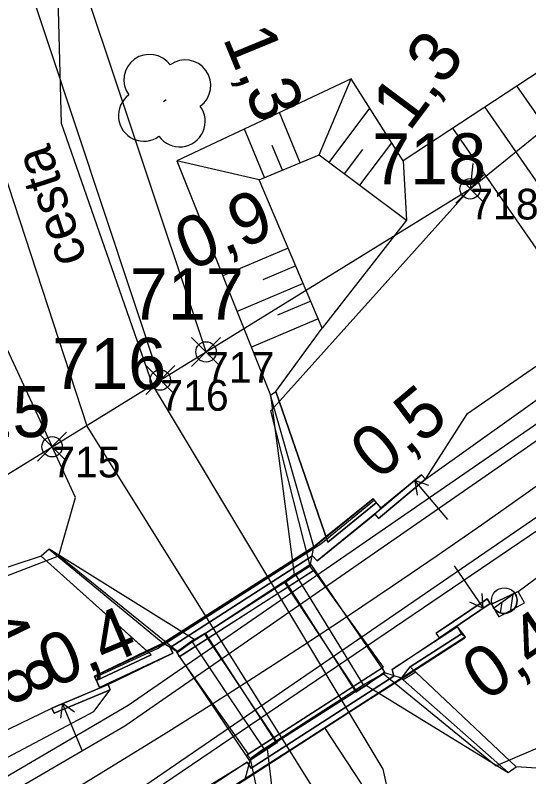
# Model space of a CAD drawing. Extents: x -800194 to -799078, y -1007177 to -1006597.
# Drawn here: x -799502.31 to -799482.23, y -1006953.32 to -1006923.53 of the extents above; entities that cross this region are included whole.
import ezdxf

# ---------------------------------------------------------------- set-up
doc = ezdxf.new("R2010")
doc.units = 0
for name, color, linetype in [('02_Osa_koleje', 7, 'Continuous'), ('Obvod stavby', 7, 'Continuous'), ('Vrstva 11', 7, 'Continuous'), ('Vrstva 12', 7, 'Continuous'), ('Vrstva 13', 7, 'Continuous'), ('Vrstva 17', 7, 'Continuous'), ('Vrstva 18', 7, 'Continuous'), ('Vrstva 4', 7, 'Continuous'), ('Vrstva 48', 7, 'Continuous'), ('Vrstva 49', 7, 'Continuous'), ('Vrstva 50', 7, 'Continuous'), ('Vrstva 51', 7, 'Continuous'), ('Vrstva 53', 7, 'Continuous'), ('Vrstva 55', 7, 'Continuous'), ('Vrstva 56', 7, 'Continuous'), ('Vrstva 60', 7, 'Continuous')]:
    doc.layers.add(name, color=color, linetype=linetype)

msp = doc.modelspace()

# ---------------------------------------------------------------- linework, layer by layer
at = {"layer": '02_Osa_koleje'}
msp.add_arc((-799651.022, -1006703.891), 292, 255.62486, 308.20516, dxfattribs=at)
at = {"layer": 'Obvod stavby'}
for p, q in [((-799485.086, -1006930.886), (-799483.954, -1006929.754)), ((-799485.086, -1006929.754), (-799483.954, -1006930.886)), ((-799495.416, -1006937.266), (-799494.284, -1006936.134)), ((-799495.416, -1006936.134), (-799494.284, -1006937.266)), ((-799497.206, -1006938.366), (-799496.074, -1006937.234)), ((-799497.206, -1006937.234), (-799496.074, -1006938.366)), ((-799501.436, -1006940.976), (-799500.304, -1006939.844)), ((-799501.436, -1006939.844), (-799500.304, -1006940.976))]:
    msp.add_line(p, q, dxfattribs=at)
msp.add_lwpolyline([(-799559.64, -1006968.48), (-799519.68, -1006952.01), (-799500.87, -1006940.41), (-799496.64, -1006937.8), (-799494.85, -1006936.7), (-799484.52, -1006930.32), (-799457.99, -1006908.8), (-799435, -1006885.17), (-799430.26, -1006880.27), (-799425.53, -1006875.38), (-799422.55, -1006864.36), (-799416.748, -1006858.798), (-799395.763, -1006879.374), (-799413.75, -1006898.23), (-799418.41, -1006902.53), (-799423.07, -1006906.83), (-799433.4, -1006916.39), (-799469.5, -1006946.86), (-799487.22, -1006958.47), (-799495.25, -1006963.74), (-799521.98, -1006977.8), (-799546.71, -1006987.83)], dxfattribs=at)
for centre in [(-799484.52, -1006930.32), (-799494.85, -1006936.7), (-799496.64, -1006937.8), (-799500.87, -1006940.41)]:
    msp.add_circle(centre, 0.4, dxfattribs=at)
at = {"layer": 'Vrstva 11'}
for p, q in [((-799482.779, -1006946.134), (-799483.593, -1006946.726)), ((-799482.944, -1006946.87), (-799482.835, -1006946.174)), ((-799483.33, -1006946.908), (-799483.264, -1006946.487))]:
    msp.add_line(p, q, dxfattribs=at)
msp.add_circle((-799483.186, -1006946.43), 0.503, dxfattribs=at)
msp.add_arc((-799483.186, -1006946.43), 0.503, 216.0719, 36.0719, dxfattribs=at)
at = {"layer": 'Vrstva 12'}
for p, q in [((-799482.39, -1006946.51), (-799482.389, -1006946.51)), ((-799483.395, -1006947.061), (-799483.396, -1006947.063))]:
    msp.add_line(p, q, dxfattribs=at)
for points in [[(-799483.686, -1006946.569), (-799483.395, -1006947.061), (-799482.39, -1006946.51), (-799482.647, -1006946.068), (-799483.686, -1006946.569)], [(-799483.686, -1006946.569), (-799483.396, -1006947.063), (-799482.389, -1006946.51), (-799482.647, -1006946.068)]]:
    msp.add_lwpolyline(points, dxfattribs=at)
at = {"layer": 'Vrstva 13'}
for p, q in [((-799486.269, -1006941.68), (-799488.105, -1006943.216)), ((-799485.395, -1006943.261), (-799486.684, -1006941.731)), ((-799485.14, -1006945.073), (-799484.016, -1006946.727)), ((-799483.858, -1006946.36), (-799485.847, -1006947.698)), ((-799498.68, -1006949.706), (-799498.679, -1006949.705)), ((-799498.598, -1006949.914), (-799498.598, -1006949.914)), ((-799499.688, -1006952.297), (-799500.461, -1006950.453)), ((-799500.882, -1006950.629), (-799500.879, -1006950.629)), ((-799500.794, -1006950.828), (-799500.793, -1006950.828))]:
    msp.add_line(p, q, dxfattribs=at)
for points in [[(-799486.419, -1006941.508), (-799488.011, -1006942.815), (-799488.249, -1006943.052)], [(-799486.419, -1006941.508), (-799487.989, -1006942.83), (-799488.249, -1006943.052), (-799488.105, -1006943.216), (-799486.271, -1006941.68), (-799486.419, -1006941.508)], [(-799486.271, -1006941.68), (-799486.269, -1006941.68), (-799486.419, -1006941.508), (-799486.419, -1006941.508)], [(-799486.132, -1006941.92), (-799486.684, -1006941.731), (-799486.591, -1006942.307)], [(-799484.545, -1006946.482), (-799484.016, -1006946.727), (-799484.049, -1006946.145)], [(-799485.713, -1006947.881), (-799485.847, -1006947.698), (-799483.855, -1006946.358), (-799483.733, -1006946.535), (-799485.713, -1006947.881)], [(-799483.734, -1006946.536), (-799483.858, -1006946.36), (-799483.855, -1006946.358)], [(-799485.713, -1006947.881), (-799483.734, -1006946.536), (-799483.733, -1006946.535)], [(-799498.598, -1006949.914), (-799500.793, -1006950.828), (-799500.882, -1006950.629), (-799498.68, -1006949.706), (-799498.598, -1006949.914)], [(-799498.598, -1006949.914), (-799498.679, -1006949.705), (-799500.879, -1006950.629), (-799500.794, -1006950.828), (-799498.598, -1006949.914)], [(-799499.991, -1006950.798), (-799500.461, -1006950.453), (-799500.545, -1006951.03)]]:
    msp.add_lwpolyline(points, dxfattribs=at)
at = {"layer": 'Vrstva 17'}
for points in [[(-799499.208, -1006949.438), (-799496.75, -1006948.302), (-799490.358, -1006944.213), (-799488.261, -1006942.491)], [(-799495.74, -1006954.93), (-799493.422, -1006953.452), (-799487.055, -1006949.386), (-799484.733, -1006947.883)]]:
    msp.add_lwpolyline(points, dxfattribs=at)
at = {"layer": 'Vrstva 18'}
for p, q in [((-799490.09, -1006944.145), (-799492.124, -1006938.252)), ((-799488.314, -1006942.445), (-799490.161, -1006943.939)), ((-799490.09, -1006944.145), (-799488.194, -1006942.597)), ((-799490.161, -1006943.939), (-799490.09, -1006944.145)), ((-799490.633, -1006944.324), (-799496.528, -1006948.097)), ((-799490.776, -1006945.086), (-799490.633, -1006944.324)), ((-799490.622, -1006944.331), (-799490.633, -1006944.324)), ((-799500.989, -1006944.417), (-799496.528, -1006948.097)), ((-799496.989, -1006948.551), (-799501.292, -1006944.69)), ((-799495.895, -1006948.622), (-799490.655, -1006945.247)), ((-799490.776, -1006945.086), (-799490.751, -1006945.022)), ((-799490.751, -1006945.022), (-799487.865, -1006949.228)), ((-799490.653, -1006945.248), (-799487.917, -1006949.036)), ((-799488.956, -1006949.979), (-799491.774, -1006945.715)), ((-799491.751, -1006945.671), (-799488.989, -1006950.004)), ((-799495.31, -1006947.953), (-799494.911, -1006947.721)), ((-799494.911, -1006947.721), (-799494.886, -1006947.696)), ((-799492.072, -1006951.961), (-799494.911, -1006947.721)), ((-799494.886, -1006947.697), (-799492.091, -1006951.998)), ((-799484.86, -1006947.727), (-799484.859, -1006947.724)), ((-799496.528, -1006948.097), (-799496.531, -1006948.126)), ((-799497.167, -1006948.391), (-799496.989, -1006948.551)), ((-799495.983, -1006948.431), (-799495.999, -1006948.451)), ((-799495.999, -1006948.451), (-799493.155, -1006952.694)), ((-799499.136, -1006949.559), (-799496.989, -1006948.551)), ((-799495.895, -1006948.62), (-799493.202, -1006952.432)), ((-799487.948, -1006949.054), (-799493.246, -1006952.463)), ((-799493.202, -1006952.432), (-799487.917, -1006949.036)), ((-799487.208, -1006949.465), (-799486.865, -1006949.018)), ((-799482.72, -1006952.931), (-799486.865, -1006949.018)), ((-799486.646, -1006949.224), (-799486.865, -1006949.018)), ((-799487.862, -1006949.253), (-799487.865, -1006949.228)), ((-799487.208, -1006949.465), (-799487.862, -1006949.253)), ((-799487.142, -1006949.523), (-799487.208, -1006949.465)), ((-799488.571, -1006949.746), (-799483.04, -1006953.154)), ((-799458.168, -1007000.066), (-799490.201, -1006951.402)), ((-799493.105, -1006952.61), (-799493.33, -1006953.427))]:
    msp.add_line(p, q, dxfattribs=at)
for points in [[(-799492.323, -1006938.391), (-799492.124, -1006938.252), (-799490.161, -1006943.939), (-799490.633, -1006944.324), (-799492.323, -1006938.391), (-799491.402, -1006945.404), (-799490.751, -1006945.022)], [(-799487.989, -1006942.83), (-799490.497, -1006944.878), (-799490.687, -1006944.683), (-799496.251, -1006948.258), (-799496.151, -1006948.479), (-799499.016, -1006949.821), (-799499.21, -1006949.384), (-799496.531, -1006948.126), (-799490.622, -1006944.331), (-799488.313, -1006942.446)], [(-799488.313, -1006942.446), (-799488.314, -1006942.445), (-799488.194, -1006942.597), (-799488.194, -1006942.597), (-799488.011, -1006942.815), (-799488.011, -1006942.815), (-799487.989, -1006942.83), (-799488.313, -1006942.446)], [(-799488.194, -1006942.597), (-799490.09, -1006944.145), (-799490.09, -1006944.145)], [(-799495.31, -1006947.953), (-799500.989, -1006944.417), (-799501.292, -1006944.69)], [(-799495.983, -1006948.431), (-799496.528, -1006948.097), (-799497.167, -1006948.391), (-799501.292, -1006944.69)], [(-799495.895, -1006948.62), (-799490.653, -1006945.248), (-799490.655, -1006945.247), (-799490.776, -1006945.086), (-799495.983, -1006948.431)], [(-799491.402, -1006945.404), (-799491.751, -1006945.671), (-799491.774, -1006945.715), (-799490.751, -1006945.022)], [(-799485.016, -1006947.459), (-799487.565, -1006949.124), (-799487.499, -1006949.378), (-799493.081, -1006952.976), (-799493.236, -1006952.753), (-799495.947, -1006954.533), (-799495.696, -1006954.958), (-799484.706, -1006947.846)], [(-799484.859, -1006947.724), (-799484.706, -1006947.846), (-799484.706, -1006947.846), (-799485.016, -1006947.459), (-799485.016, -1006947.459), (-799484.86, -1006947.727)], [(-799495.31, -1006947.953), (-799495.999, -1006948.451), (-799494.886, -1006947.697), (-799494.886, -1006947.696)], [(-799484.706, -1006947.846), (-799487.208, -1006949.465), (-799493.33, -1006953.427), (-799495.696, -1006954.958), (-799495.696, -1006954.958)], [(-799486.865, -1006949.018), (-799484.859, -1006947.724)], [(-799484.86, -1006947.727), (-799486.865, -1006949.018), (-799486.865, -1006949.018)], [(-799497.167, -1006948.391), (-799499.209, -1006949.385), (-799499.21, -1006949.384)], [(-799495.895, -1006948.62), (-799495.895, -1006948.622), (-799495.983, -1006948.431)], [(-799496.989, -1006948.551), (-799496.989, -1006948.551), (-799499.13, -1006949.555)], [(-799493.155, -1006952.694), (-799493.105, -1006952.61), (-799487.862, -1006949.253), (-799487.948, -1006949.054), (-799487.917, -1006949.036)], [(-799499.209, -1006949.385), (-799499.136, -1006949.559), (-799499.13, -1006949.555), (-799499.015, -1006949.821), (-799499.016, -1006949.821)], [(-799488.571, -1006949.746), (-799488.989, -1006950.004), (-799488.956, -1006949.979), (-799487.865, -1006949.228), (-799488.571, -1006949.746)], [(-799483.04, -1006953.154), (-799482.72, -1006952.931), (-799486.646, -1006949.224), (-799487.142, -1006949.523), (-799483.04, -1006953.154)], [(-799492.448, -1006952.232), (-799492.072, -1006951.961), (-799492.091, -1006951.998), (-799493.155, -1006952.694)], [(-799492.007, -1006959.466), (-799491.611, -1006959.287), (-799492.448, -1006952.232), (-799493.155, -1006952.694)], [(-799493.105, -1006952.61), (-799493.246, -1006952.463), (-799493.202, -1006952.432)]]:
    msp.add_lwpolyline(points, dxfattribs=at)
at = {"layer": 'Vrstva 4'}
for points in [[(-799510.394, -1006958.536), (-799498.027, -1006951.328), (-799477.988, -1006937.435), (-799460.33, -1006923.117), (-799451.862, -1006915.581), (-799443.604, -1006907.9), (-799435.444, -1006900.067), (-799428.64, -1006893.299), (-799422.817, -1006887.511), (-799415.998, -1006880.595), (-799408.158, -1006872.652), (-799401.02, -1006864.85)], [(-799509.248, -1006960.724), (-799497.456, -1006953.809), (-799476.495, -1006939.437), (-799458.707, -1006924.982), (-799450.277, -1006917.43), (-799441.932, -1006909.717), (-799433.783, -1006901.867), (-799426.9, -1006895.092), (-799421.037, -1006889.182), (-799414.218, -1006882.281), (-799406.443, -1006874.417), (-799398.609, -1006866.93)], [(-799511.236, -1006957.129), (-799499.236, -1006950.771), (-799498.598, -1006949.914), (-799498.679, -1006949.705), (-799496.151, -1006948.479), (-799496.251, -1006948.258), (-799490.687, -1006944.683), (-799490.497, -1006944.878), (-799488.249, -1006943.052), (-799488.105, -1006943.216), (-799486.269, -1006941.68), (-799478.997, -1006936.484), (-799474.568, -1006932.916), (-799474.237, -1006932.694), (-799461.519, -1006921.99), (-799452.935, -1006914.372), (-799444.695, -1006906.886), (-799436.579, -1006898.932), (-799429.629, -1006892.192), (-799429.07, -1006892.727), (-799423.479, -1006886.901), (-799416.56, -1006880.007), (-799417.085, -1006879.46), (-799415.349, -1006878.386)], [(-799510.726, -1006958.045), (-799497.901, -1006950.516), (-799478.36, -1006937.055), (-799461.534, -1006923.53), (-799452.128, -1006915.305), (-799443.894, -1006907.632), (-799435.739, -1006899.754), (-799428.922, -1006893.007), (-799423.223, -1006887.256), (-799416.277, -1006880.269), (-799414.896, -1006878.87)], [(-799509.087, -1006961.127), (-799497.277, -1006954.118), (-799476.183, -1006939.802), (-799458.586, -1006925.284), (-799449.914, -1006917.869), (-799441.499, -1006910.139), (-799433.371, -1006902.28), (-799426.451, -1006895.478), (-799420.657, -1006889.585), (-799413.85, -1006882.742), (-799412.388, -1006881.287)], [(-799507.817, -1006962.779), (-799497.104, -1006956.83), (-799497.4, -1006955.599), (-799497.585, -1006955.395), (-799495.628, -1006953.965), (-799495.505, -1006954.146), (-799493.236, -1006952.753), (-799493.081, -1006952.976), (-799487.499, -1006949.378), (-799487.565, -1006949.124), (-799485.713, -1006947.881), (-799485.847, -1006947.698), (-799483.858, -1006946.36), (-799483.734, -1006946.536), (-799483.686, -1006946.569), (-799482.647, -1006946.068), (-799475.489, -1006940.774), (-799457.684, -1006926.366)]]:
    msp.add_lwpolyline(points, dxfattribs=at)
at = {"layer": 'Vrstva 48'}
for p, q in [((-799477.319, -1006934.06), (-799482.69, -1006926.295)), ((-799491.172, -1006929.304), (-799491.98, -1006927.341)), ((-799490.032, -1006929.287), (-799488.444, -1006927.16)), ((-799478.552, -1006934.913), (-799483.943, -1006927.119)), ((-799479.786, -1006935.767), (-799485.197, -1006927.943)), ((-799492.559, -1006929.875), (-799493.339, -1006927.982)), ((-799488.83, -1006930.184), (-799487.586, -1006928.519)), ((-799491.865, -1006929.589), (-799492.262, -1006928.625)), ((-799489.431, -1006929.736), (-799488.723, -1006928.788)), ((-799491.636, -1006932.643), (-799494.189, -1006933.727)), ((-799491.343, -1006933.333), (-799492.626, -1006933.878)), ((-799491.05, -1006934.024), (-799493.632, -1006935.12)), ((-799490.757, -1006934.714), (-799492.055, -1006935.265)), ((-799490.463, -1006935.405), (-799493.074, -1006936.513))]:
    msp.add_line(p, q, dxfattribs=at)
at = {"layer": 'Vrstva 49'}
for p, q in [((-799490.423, -1006928.995), (-799489.168, -1006926.015)), ((-799492.773, -1006929.963), (-799495.987, -1006929.231)), ((-799492.124, -1006938.252), (-799490.308, -1006935.771))]:
    msp.add_line(p, q, dxfattribs=at)
for points in [[(-799429.125, -1006891.656), (-799433.133, -1006889.484), (-799437.572, -1006888.963), (-799439.693, -1006890.332), (-799461.15, -1006912.135), (-799487.142, -1006929.222), (-799487.006, -1006931.546), (-799490.308, -1006935.771)], [(-799490.09, -1006944.145), (-799488.194, -1006942.597), (-799488.011, -1006942.815), (-799488.011, -1006942.815), (-799486.419, -1006941.508), (-799486.269, -1006941.68), (-799484.618, -1006939.109), (-799474.926, -1006932.405), (-799474.596, -1006932.171), (-799461.519, -1006921.99), (-799452.935, -1006914.372), (-799445.566, -1006906.106), (-799432.588, -1006892.596), (-799429.125, -1006891.656)], [(-799486.865, -1006949.018), (-799484.86, -1006947.727), (-799485.016, -1006947.459), (-799485.713, -1006947.881), (-799483.734, -1006946.536), (-799483.686, -1006946.569), (-799483.396, -1006947.063), (-799482.389, -1006946.51), (-799482.647, -1006946.068), (-799475.489, -1006940.774), (-799464.892, -1006933.871), (-799456.989, -1006927.138), (-799455.117, -1006925.642), (-799440.165, -1006911.165), (-799428.918, -1006899.95), (-799428.299, -1006900.544), (-799427.466, -1006899.73), (-799428.131, -1006899.117), (-799426.509, -1006898.237), (-799425.17, -1006895.342)], [(-799423.903, -1006906.911), (-799427.313, -1006910.033), (-799439.866, -1006919.177), (-799453.667, -1006933.596), (-799478.523, -1006953.199), (-799482.72, -1006952.931), (-799486.865, -1006949.018)], [(-799487.142, -1006929.222), (-799489.168, -1006926.015), (-799495.987, -1006929.231), (-799492.323, -1006938.391), (-799492.124, -1006938.252)], [(-799490.308, -1006935.771), (-799492.773, -1006929.963), (-799490.423, -1006928.995), (-799487.006, -1006931.546)], [(-799492.124, -1006938.252), (-799490.09, -1006944.145)], [(-799496.989, -1006948.551), (-799501.292, -1006944.69), (-799510.22, -1006947.622)], [(-799512.053, -1006955.956), (-799509.8, -1006954.937), (-799509.204, -1006954.659), (-799500.879, -1006950.629), (-799498.679, -1006949.705), (-799499.015, -1006949.821), (-799499.13, -1006949.555), (-799496.989, -1006948.551)]]:
    msp.add_lwpolyline(points, dxfattribs=at)
at = {"layer": 'Vrstva 50'}
msp.add_line((-799496.517, -1006926.907), (-799496.403, -1006926.823), dxfattribs=at)
for centre, start, end in [((-799497.059, -1006926.062), 36.0719, 216.0719), ((-799495.662, -1006926.281), 306.0719, 126.0719), ((-799497.278, -1006927.459), 126.0719, 306.0719), ((-799495.881, -1006927.678), 216.0719, 36.0719)]:
    msp.add_arc(centre, 1, start, end, dxfattribs=at)
at = {"layer": 'Vrstva 51'}
for points in [[(-799487.284, -1006968.607), (-799490.087, -1006954.678), (-799499.499, -1006939.61), (-799503.236, -1006928.194), (-799504.313, -1006911.364)], [(-799484.495, -1006968.489), (-799487.918, -1006953.016), (-799496.949, -1006937.979), (-799500.5, -1006927.768), (-799500.929, -1006911.492)]]:
    msp.add_lwpolyline(points, dxfattribs=at)
at = {"layer": 'Vrstva 53'}
msp.add_lwpolyline([(-799559.64, -1006968.48), (-799519.68, -1006952.01), (-799500.87, -1006940.41), (-799496.64, -1006937.8), (-799494.85, -1006936.7), (-799484.519, -1006930.319), (-799457.99, -1006908.8), (-799435, -1006885.17), (-799430.26, -1006880.27), (-799425.53, -1006875.38), (-799422.55, -1006864.36), (-799390.88, -1006834), (-799358.35, -1006806.65), (-799352.29, -1006801.56), (-799330.91, -1006783.58), (-799314.235, -1006766.649)], dxfattribs=at)
at = {"layer": 'Vrstva 55'}
for p, q in [((-799496.64, -1006937.8), (-799494.85, -1006936.7)), ((-799500.87, -1006940.41), (-799496.64, -1006937.8)), ((-799519.68, -1006952.01), (-799500.87, -1006940.41))]:
    msp.add_line(p, q, dxfattribs=at)
for points in [[(-799494.85, -1006936.7), (-799484.52, -1006930.32), (-799457.99, -1006908.8), (-799435, -1006885.17)], [(-799494.85, -1006936.7), (-799505.77, -1006904), (-799506.49, -1006901.85)], [(-799496.64, -1006937.8), (-799507.65, -1006904.69), (-799515.98, -1006907.74), (-799500.87, -1006940.41)], [(-799519.68, -1006952.01), (-799500.6, -1006944.68), (-799499.96, -1006942.39), (-799500.87, -1006940.41)]]:
    msp.add_lwpolyline(points, dxfattribs=at)
at = {"layer": 'Vrstva 56'}
for p, q in [((-799484.415, -1006929.325), (-799484.519, -1006930.319)), ((-799484.52, -1006930.32), (-799492.32, -1006939.01)), ((-799490.79, -1006945.02), (-799492.32, -1006939.01)), ((-799495.94, -1006948.45), (-799500.6, -1006944.68)), ((-799491.36, -1006945.39), (-799490.79, -1006945.02)), ((-799495.39, -1006948.04), (-799491.36, -1006945.39)), ((-799491.36, -1006945.39), (-799490.06, -1006947.5)), ((-799469.5, -1006946.86), (-799483.5, -1006952.89)), ((-799490.06, -1006947.5), (-799488.7, -1006949.72)), ((-799495.39, -1006948.04), (-799495.94, -1006948.45)), ((-799495.39, -1006948.04), (-799494.03, -1006950.08)), ((-799488.7, -1006949.72), (-799487.92, -1006949.28)), ((-799487.92, -1006949.28), (-799483.5, -1006952.89)), ((-799492.59, -1006952.23), (-799488.7, -1006949.72)), ((-799494.03, -1006950.08), (-799492.59, -1006952.23)), ((-799492.59, -1006952.23), (-799493.13, -1006952.62)), ((-799493.13, -1006952.62), (-799491.86, -1006958.5))]:
    msp.add_line(p, q, dxfattribs=at)
at = {"layer": 'Vrstva 60'}
for p, q in [((-799484.52, -1006930.32), (-799484.52, -1006930.32)), ((-799494.85, -1006936.7), (-799494.85, -1006936.7)), ((-799496.64, -1006937.8), (-799496.64, -1006937.8)), ((-799500.87, -1006940.41), (-799500.87, -1006940.41))]:
    msp.add_line(p, q, dxfattribs=at)

# ---------------------------------------------------------------- texts
at = {"layer": 'Obvod stavby'}
for s, p in [('718', (-799488.355, -1006930.151)), ('717', (-799497.83, -1006935.436)), ('716', (-799500.869, -1006938.151)), ('715', (-799505.397, -1006940.033))]:
    msp.add_text(s, height=2, rotation=360, dxfattribs=at).set_placement(p)
at = {"layer": 'Vrstva 13'}
for s, rotation, p in [('0,5', 40.0987, (-799488.121, -1006941.773)), ('0,4', 22.7824, (-799500.862, -1006949.865)), ('0,4', 34.2014, (-799483.93, -1006950.409))]:
    msp.add_text(s, height=2, rotation=rotation, dxfattribs=at).set_placement(p)
at = {"layer": 'Vrstva 48'}
for s, rotation, p in [('1,3', 292.3875, (-799494.208, -1006924.423)), ('1,3', 53.2564, (-799486.904, -1006928.121)), ('0,9', 22.9971, (-799495.498, -1006933.548)), ('4,8', 295.8309, (-799504.015, -1006947.319))]:
    msp.add_text(s, height=2, rotation=rotation, dxfattribs=at).set_placement(p)
at = {"layer": 'Vrstva 51'}
msp.add_text('cesta', height=1.5, rotation=108.1257, dxfattribs=at).set_placement((-799499.492, -1006933.062))
at = {"layer": 'Vrstva 60'}
for s, p in [('718', (-799484.52, -1006931.52)), ('717', (-799494.85, -1006937.9)), ('716', (-799496.64, -1006939)), ('715', (-799500.87, -1006941.61))]:
    msp.add_text(s, height=1.2, dxfattribs=at).set_placement(p)

doc.saveas('drawing.dxf')
